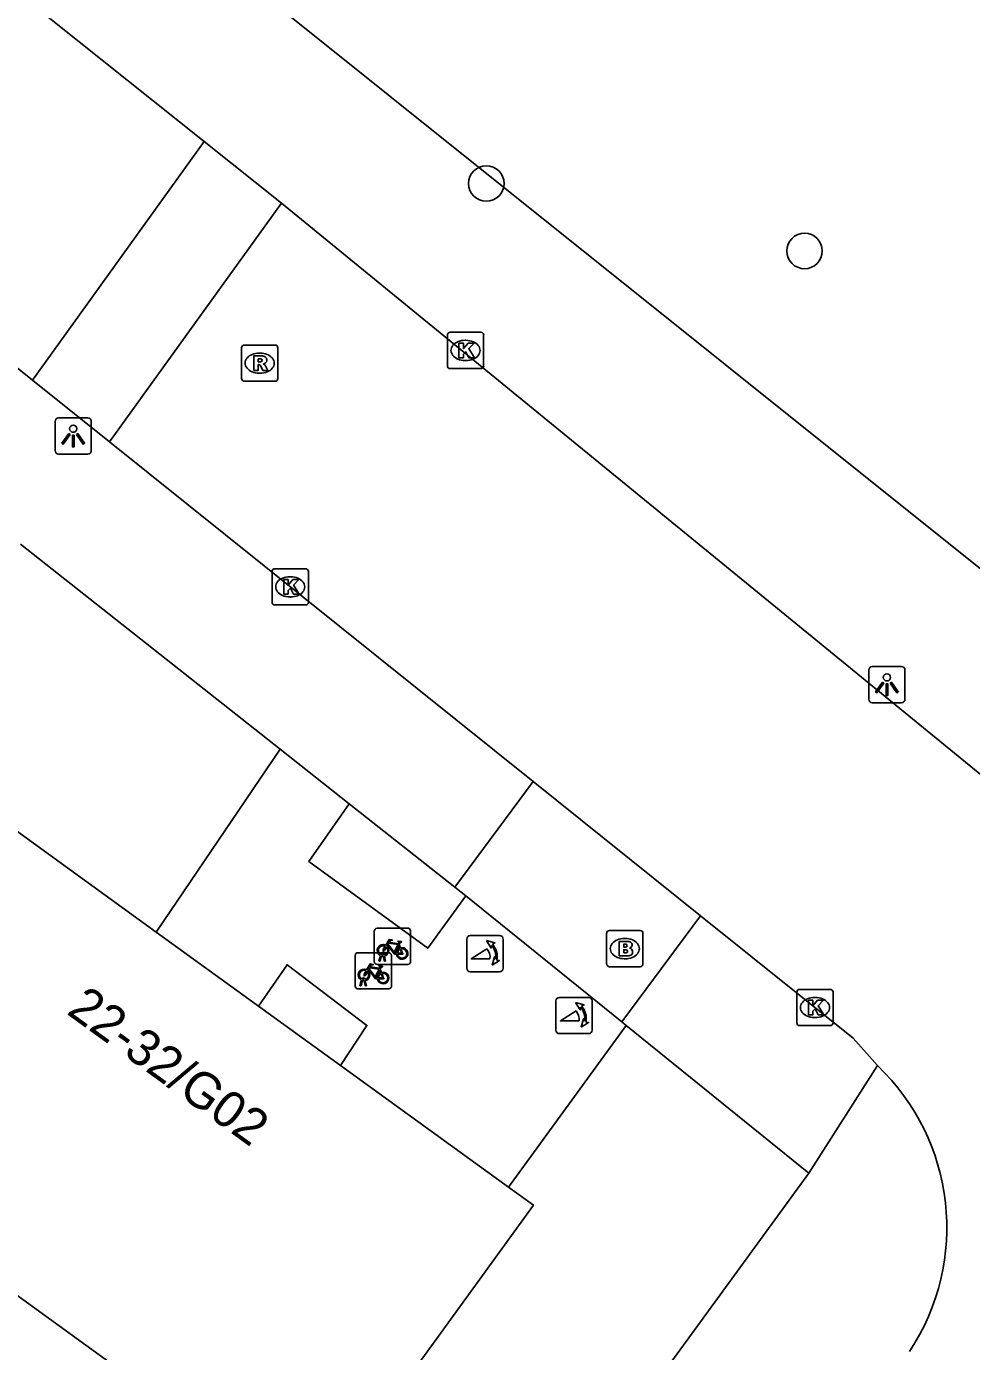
# Model space of a CAD drawing. Extents: x 159675 to 160530, y 382179 to 382901.
# Drawn here: x 160377.56 to 160403.62, y 382615.6 to 382652.14 of the extents above; entities that cross this region are included whole.
import ezdxf

# ---------------------------------------------------------------- set-up
doc = ezdxf.new("R2010")
doc.units = 0
for name, color, linetype in [('IMGEO_Boom', 7, 'Continuous'), ('IMGEO_Brandkraan', 7, 'Continuous'), ('IMGEO_Fietsenrek', 7, 'Continuous'), ('IMGEO_Kolk', 7, 'Continuous'), ('IMGEO_Lichtpunt', 7, 'Continuous'), ('IMGEO_Pand', 7, 'Continuous'), ('IMGEO_Pand_nummerreeks', 7, 'Continuous'), ('IMGEO_Poller', 7, 'Continuous'), ('IMGEO_Rijbaan_lokaal_gesloten', 7, 'Continuous'), ('IMGEO_Rijbaan_lokaal_open', 7, 'Continuous'), ('IMGEO_Rioolput', 7, 'Continuous'), ('IMGEO_Voetpad_open', 7, 'Continuous')]:
    doc.layers.add(name, color=color, linetype=linetype)

msp = doc.modelspace()

# ---------------------------------------------------------------- linework, layer by layer
at = {"layer": 'IMGEO_Boom'}
for centre in [(160390.238, 382647.812), (160399.015, 382645.95)]:
    msp.add_circle(centre, 0.489, dxfattribs=at)
at = {"layer": 'IMGEO_Brandkraan'}
for p, q in [((160393.557, 382626.284), (160393.557, 382627.136)), ((160393.632, 382627.21), (160394.484, 382627.21)), ((160394.045, 382626.99), (160394.07, 382626.99)), ((160394.558, 382627.136), (160394.558, 382626.284)), ((160394.484, 382626.21), (160393.632, 382626.21)), ((160394.068, 382626.43), (160394.043, 382626.43))]:
    msp.add_line(p, q, dxfattribs=at)
for points in [[(160393.557, 382626.284), (160393.557, 382627.136)], [(160393.632, 382627.21), (160394.484, 382627.21)], [(160394.558, 382627.136), (160394.558, 382626.284)], [(160393.905, 382626.91), (160393.905, 382626.51), (160394.118, 382626.51)], [(160394.136, 382626.91), (160393.905, 382626.91)], [(160394.084, 382626.829), (160394.03, 382626.829), (160394.03, 382626.753)], [(160394.03, 382626.753), (160394.083, 382626.753)], [(160394.092, 382626.677), (160394.03, 382626.677), (160394.03, 382626.596)], [(160394.03, 382626.596), (160394.092, 382626.596)], [(160394.484, 382626.21), (160393.632, 382626.21)]]:
    msp.add_lwpolyline(points, dxfattribs=at)
for centre, radius, start, end in [((160393.634, 382627.134), 0.0765, 91.552, 178.448), ((160393.634, 382627.134), 0.0765, 91.552, 178.448), ((160394.482, 382627.134), 0.0765, 1.552, 88.448), ((160394.482, 382627.134), 0.0765, 1.552, 88.448), ((160394.085, 382626.791), 0.0379, 267.8285, 90.9355), ((160394.093, 382626.636), 0.0404, 269.8759, 90.5077), ((160394.14, 382626.765), 0.145, 59.4692, 91.5367), ((160394.165, 382626.812), 0.0922, 285.5137, 58.1501), ((160394.17, 382626.62), 0.105, 301.3115, 78.989), ((160393.634, 382626.286), 0.0765, 181.552, 268.448), ((160393.634, 382626.286), 0.0765, 181.552, 268.448), ((160394.124, 382626.761), 0.251, 268.6676, 293.5347), ((160394.482, 382626.286), 0.0765, 271.552, 358.448), ((160394.482, 382626.286), 0.0765, 271.552, 358.448)]:
    msp.add_arc(centre, radius, start, end, dxfattribs=at)
for centre, major_axis, ratio, start_param, end_param in [((160394.044, 382626.71), (-0.387, 0.002), 0.722429, 4.712389, 7.853982), ((160394.069, 382626.71), (-0.39, 0.002), 0.717154, 1.570796, 4.712389)]:
    msp.add_ellipse(centre, major_axis=major_axis, ratio=ratio, start_param=start_param, end_param=end_param, dxfattribs=at)
at = {"layer": 'IMGEO_Fietsenrek'}
for p, q in [((160387.15, 382626.351), (160387.15, 382627.192)), ((160387.15, 382627.192), (160387.15, 382626.351)), ((160387.225, 382627.276), (160388.066, 382627.276)), ((160388.066, 382627.276), (160387.225, 382627.276)), ((160388.15, 382627.201), (160388.15, 382626.36)), ((160388.15, 382626.36), (160388.15, 382627.201)), ((160386.7, 382626.598), (160387.541, 382626.598)), ((160387.541, 382626.598), (160386.7, 382626.598)), ((160387.837, 382626.825), (160387.873, 382626.73)), ((160386.625, 382625.673), (160386.625, 382626.514)), ((160386.625, 382626.514), (160386.625, 382625.673)), ((160388.075, 382626.276), (160387.234, 382626.276)), ((160387.234, 382626.276), (160388.075, 382626.276)), ((160387.277, 382626.36), (160387.316, 382626.52)), ((160387.311, 382626.36), (160387.277, 382626.36)), ((160387.346, 382626.508), (160387.311, 382626.36)), ((160387.388, 382626.532), (160387.387, 382626.536)), ((160387.429, 382626.36), (160387.395, 382626.502)), ((160387.419, 382626.543), (160387.42, 382626.536)), ((160387.427, 382626.506), (160387.462, 382626.36)), ((160387.462, 382626.36), (160387.429, 382626.36)), ((160387.625, 382626.523), (160387.625, 382625.682)), ((160387.625, 382625.682), (160387.625, 382626.523)), ((160386.752, 382625.682), (160386.791, 382625.842)), ((160386.863, 382625.854), (160386.862, 382625.858)), ((160386.894, 382625.865), (160386.895, 382625.858)), ((160387.312, 382626.147), (160387.348, 382626.052)), ((160387.55, 382625.598), (160386.709, 382625.598)), ((160386.709, 382625.598), (160387.55, 382625.598)), ((160386.786, 382625.682), (160386.752, 382625.682)), ((160386.821, 382625.83), (160386.786, 382625.682)), ((160386.904, 382625.682), (160386.87, 382625.824)), ((160386.902, 382625.828), (160386.937, 382625.682)), ((160386.937, 382625.682), (160386.904, 382625.682))]:
    msp.add_line(p, q, dxfattribs=at)
for points in [[(160387.463, 382626.802), (160387.558, 382626.966), (160387.644, 382626.952), (160387.646, 382626.943), (160387.59, 382626.932), (160387.563, 382626.887), (160387.819, 382626.846)], [(160387.484, 382626.75), (160387.432, 382626.66), (160387.392, 382626.635), (160387.393, 382626.682), (160387.448, 382626.776)], [(160387.759, 382626.558), (160387.709, 382626.558), (160387.518, 382626.809), (160387.499, 382626.777)], [(160387.806, 382626.821), (160387.549, 382626.862), (160387.532, 382626.833), (160387.699, 382626.613), (160387.806, 382626.821)], [(160387.854, 382626.723), (160387.824, 382626.8), (160387.715, 382626.582), (160387.758, 382626.582)], [(160387.788, 382626.582), (160387.908, 382626.581), (160387.864, 382626.695)], [(160387.884, 382626.702), (160387.939, 382626.557), (160387.789, 382626.557)], [(160387.819, 382626.846), (160387.844, 382626.895), (160387.838, 382626.899), (160387.815, 382626.903), (160387.803, 382626.91), (160387.802, 382626.913), (160387.804, 382626.918), (160387.899, 382626.903), (160387.901, 382626.893), (160387.891, 382626.88), (160387.879, 382626.874), (160387.865, 382626.88), (160387.837, 382626.825)], [(160386.938, 382626.124), (160387.033, 382626.288), (160387.119, 382626.274), (160387.121, 382626.265), (160387.065, 382626.254), (160387.038, 382626.209), (160387.294, 382626.168)], [(160387.294, 382626.168), (160387.319, 382626.217), (160387.313, 382626.221), (160387.29, 382626.225), (160387.278, 382626.232), (160387.277, 382626.235), (160387.279, 382626.24), (160387.374, 382626.225), (160387.376, 382626.215), (160387.366, 382626.202), (160387.354, 382626.196), (160387.34, 382626.202), (160387.312, 382626.147)], [(160386.959, 382626.072), (160386.907, 382625.982), (160386.867, 382625.957), (160386.868, 382626.004), (160386.923, 382626.098)], [(160387.234, 382625.88), (160387.184, 382625.88), (160386.993, 382626.131), (160386.974, 382626.099)], [(160387.281, 382626.143), (160387.024, 382626.184), (160387.007, 382626.155), (160387.174, 382625.935), (160387.281, 382626.143)], [(160387.329, 382626.045), (160387.299, 382626.122), (160387.19, 382625.904), (160387.233, 382625.904)], [(160387.263, 382625.904), (160387.383, 382625.903), (160387.339, 382626.017)], [(160387.359, 382626.024), (160387.414, 382625.879), (160387.264, 382625.879)]]:
    msp.add_lwpolyline(points, dxfattribs=at)
for centre, radius, start, end in [((160387.228, 382627.198), 0.0779, 92.4484, 184.2845), ((160387.228, 382627.198), 0.0779, 92.4484, 184.2845), ((160388.072, 382627.198), 0.0779, 2.4484, 94.2845), ((160388.072, 382627.198), 0.0779, 2.4484, 94.2845), ((160386.703, 382626.52), 0.0779, 92.4484, 184.2845), ((160386.703, 382626.52), 0.0779, 92.4484, 184.2845), ((160387.39, 382626.661), 0.159, 62.6766, 242.1369), ((160387.39, 382626.661), 0.129, 63.3192, 238.903), ((160387.37, 382626.532), 0.0499, 12.8025, 158.6934), ((160387.39, 382626.661), 0.129, 283.6043, 43.4302), ((160387.39, 382626.661), 0.159, 283.5766, 46.6042), ((160387.547, 382626.52), 0.0779, 2.4484, 94.2845), ((160387.547, 382626.52), 0.0779, 2.4484, 94.2845), ((160387.917, 382626.577), 0.159, 113.3408, 178.3217), ((160387.917, 382626.577), 0.159, 187.0065, 105.7708), ((160387.917, 382626.577), 0.129, 113.923, 177.9556), ((160387.917, 382626.577), 0.129, 188.6715, 104.5883), ((160387.228, 382626.354), 0.0779, 182.4484, 274.2845), ((160387.228, 382626.354), 0.0779, 182.4484, 274.2845), ((160387.39, 382626.661), 0.159, 253.9967, 271.7867), ((160387.37, 382626.532), 0.0174, 12.8025, 163.4502), ((160387.39, 382626.661), 0.129, 253.415, 269.0204), ((160388.072, 382626.354), 0.0779, 272.4484, 4.2845), ((160388.072, 382626.354), 0.0779, 272.4484, 4.2845), ((160386.865, 382625.983), 0.159, 62.6766, 242.1369), ((160386.865, 382625.983), 0.129, 63.3192, 238.903), ((160386.845, 382625.854), 0.0499, 12.8025, 158.6934), ((160386.845, 382625.854), 0.0174, 12.8025, 163.4502), ((160386.865, 382625.983), 0.129, 253.415, 269.0204), ((160386.865, 382625.983), 0.129, 283.6043, 43.4302), ((160386.865, 382625.983), 0.159, 283.5766, 46.6042), ((160387.392, 382625.899), 0.159, 113.3408, 178.3217), ((160387.392, 382625.899), 0.159, 187.0065, 105.7708), ((160387.392, 382625.899), 0.129, 113.923, 177.9556), ((160387.392, 382625.899), 0.129, 188.6715, 104.5883), ((160386.703, 382625.676), 0.0779, 182.4484, 274.2845), ((160386.703, 382625.676), 0.0779, 182.4484, 274.2845), ((160386.865, 382625.983), 0.159, 253.9967, 271.7867), ((160387.547, 382625.676), 0.0779, 272.4484, 4.2845), ((160387.547, 382625.676), 0.0779, 272.4484, 4.2845)]:
    msp.add_arc(centre, radius, start, end, dxfattribs=at)
at = {"layer": 'IMGEO_Kolk'}
for p, q in [((160389.164, 382642.781), (160389.164, 382643.633)), ((160389.239, 382643.707), (160390.091, 382643.707)), ((160389.652, 382643.487), (160389.677, 382643.487)), ((160390.165, 382643.633), (160390.165, 382642.781)), ((160390.091, 382642.707), (160389.239, 382642.707)), ((160389.675, 382642.927), (160389.65, 382642.927)), ((160384.405, 382637.187), (160385.257, 382637.187)), ((160384.33, 382636.261), (160384.33, 382637.113)), ((160384.818, 382636.967), (160384.843, 382636.967)), ((160385.331, 382637.113), (160385.331, 382636.261)), ((160385.257, 382636.187), (160384.405, 382636.187)), ((160384.841, 382636.407), (160384.816, 382636.407)), ((160398.801, 382624.66), (160398.801, 382625.512)), ((160398.876, 382625.586), (160399.728, 382625.586)), ((160399.802, 382625.512), (160399.802, 382624.66)), ((160399.289, 382625.366), (160399.314, 382625.366)), ((160399.312, 382624.806), (160399.287, 382624.806)), ((160399.728, 382624.586), (160398.876, 382624.586))]:
    msp.add_line(p, q, dxfattribs=at)
for points in [[(160389.164, 382642.781), (160389.164, 382643.633)], [(160389.239, 382643.707), (160390.091, 382643.707)], [(160389.485, 382643.407), (160389.608, 382643.407), (160389.608, 382643.256), (160389.738, 382643.407), (160389.902, 382643.407), (160389.756, 382643.256), (160389.909, 382643.007), (160389.757, 382643.007), (160389.672, 382643.171), (160389.608, 382643.104), (160389.608, 382643.007), (160389.485, 382643.007), (160389.485, 382643.407)], [(160390.165, 382643.633), (160390.165, 382642.781)], [(160390.091, 382642.707), (160389.239, 382642.707)], [(160384.405, 382637.187), (160385.257, 382637.187)], [(160384.33, 382636.261), (160384.33, 382637.113)], [(160384.651, 382636.887), (160384.774, 382636.887), (160384.774, 382636.736), (160384.904, 382636.887), (160385.068, 382636.887), (160384.922, 382636.736), (160385.075, 382636.487), (160384.923, 382636.487), (160384.838, 382636.651), (160384.774, 382636.584), (160384.774, 382636.487), (160384.651, 382636.487), (160384.651, 382636.887)], [(160385.331, 382637.113), (160385.331, 382636.261)], [(160385.257, 382636.187), (160384.405, 382636.187)], [(160398.801, 382624.66), (160398.801, 382625.512)], [(160398.876, 382625.586), (160399.728, 382625.586)], [(160399.802, 382625.512), (160399.802, 382624.66)], [(160399.122, 382625.286), (160399.245, 382625.286), (160399.245, 382625.135), (160399.375, 382625.286), (160399.539, 382625.286), (160399.393, 382625.135), (160399.546, 382624.886), (160399.394, 382624.886), (160399.309, 382625.05), (160399.245, 382624.983), (160399.245, 382624.886), (160399.122, 382624.886), (160399.122, 382625.286)], [(160399.728, 382624.586), (160398.876, 382624.586)]]:
    msp.add_lwpolyline(points, dxfattribs=at)
for centre, start, end in [((160389.241, 382643.631), 91.552, 178.448), ((160389.241, 382643.631), 91.552, 178.448), ((160390.089, 382643.631), 1.552, 88.448), ((160390.089, 382643.631), 1.552, 88.448), ((160389.241, 382642.783), 181.552, 268.448), ((160389.241, 382642.783), 181.552, 268.448), ((160390.089, 382642.783), 271.552, 358.448), ((160390.089, 382642.783), 271.552, 358.448), ((160384.407, 382637.111), 91.552, 178.448), ((160384.407, 382637.111), 91.552, 178.448), ((160385.255, 382637.111), 1.552, 88.448), ((160385.255, 382637.111), 1.552, 88.448), ((160384.407, 382636.263), 181.552, 268.448), ((160384.407, 382636.263), 181.552, 268.448), ((160385.255, 382636.263), 271.552, 358.448), ((160385.255, 382636.263), 271.552, 358.448), ((160398.878, 382625.51), 91.552, 178.448), ((160398.878, 382625.51), 91.552, 178.448), ((160399.726, 382625.51), 1.552, 88.448), ((160399.726, 382625.51), 1.552, 88.448), ((160398.878, 382624.662), 181.552, 268.448), ((160398.878, 382624.662), 181.552, 268.448), ((160399.726, 382624.662), 271.552, 358.448), ((160399.726, 382624.662), 271.552, 358.448)]:
    msp.add_arc(centre, 0.0765, start, end, dxfattribs=at)
for centre, major_axis, ratio, start_param, end_param in [((160389.651, 382643.207), (-0.387, 0.002), 0.722429, 4.712389, 7.853982), ((160389.676, 382643.207), (-0.39, 0.002), 0.717154, 1.570796, 4.712389), ((160384.817, 382636.687), (-0.387, 0.002), 0.722429, 4.712389, 7.853982), ((160384.842, 382636.687), (-0.39, 0.002), 0.717154, 1.570796, 4.712389), ((160399.288, 382625.086), (-0.387, 0.002), 0.722429, 4.712389, 7.853982), ((160399.313, 382625.086), (-0.39, 0.002), 0.717154, 1.570796, 4.712389)]:
    msp.add_ellipse(centre, major_axis=major_axis, ratio=ratio, start_param=start_param, end_param=end_param, dxfattribs=at)
at = {"layer": 'IMGEO_Lichtpunt'}
for p, q in [((160378.349, 382641.251), (160378.349, 382640.444)), ((160378.349, 382641.251), (160378.349, 382640.444)), ((160379.251, 382641.346), (160378.443, 382641.346)), ((160379.251, 382641.346), (160378.443, 382641.346)), ((160379.345, 382640.444), (160379.345, 382641.251)), ((160379.345, 382640.444), (160379.345, 382641.251)), ((160378.443, 382640.35), (160379.251, 382640.35)), ((160378.443, 382640.35), (160379.251, 382640.35)), ((160400.787, 382634.393), (160400.787, 382633.586)), ((160400.787, 382634.393), (160400.787, 382633.586)), ((160401.689, 382634.488), (160400.881, 382634.488)), ((160401.689, 382634.488), (160400.881, 382634.488)), ((160401.783, 382633.586), (160401.783, 382634.393)), ((160401.783, 382633.586), (160401.783, 382634.393)), ((160400.881, 382633.492), (160401.689, 382633.492)), ((160400.881, 382633.492), (160401.689, 382633.492))]:
    msp.add_line(p, q, dxfattribs=at)
for points in [[(160378.723, 382640.915), (160378.762, 382640.887), (160378.574, 382640.625), (160378.536, 382640.652), (160378.723, 382640.915)], [(160378.825, 382640.867), (160378.872, 382640.867), (160378.872, 382640.545), (160378.825, 382640.545), (160378.825, 382640.867)], [(160378.935, 382640.887), (160378.973, 382640.914), (160379.16, 382640.652), (160379.121, 382640.624), (160378.935, 382640.887)], [(160401.161, 382634.057), (160401.2, 382634.029), (160401.012, 382633.767), (160400.974, 382633.794), (160401.161, 382634.057)], [(160401.263, 382634.009), (160401.31, 382634.009), (160401.31, 382633.687), (160401.263, 382633.687), (160401.263, 382634.009)], [(160401.373, 382634.029), (160401.411, 382634.056), (160401.598, 382633.794), (160401.559, 382633.766), (160401.373, 382634.029)]]:
    msp.add_lwpolyline(points, dxfattribs=at)
for centre in [(160378.848, 382641.049), (160401.286, 382634.191)]:
    msp.add_circle(centre, 0.0994, dxfattribs=at)
for centre, start, end in [((160378.443, 382641.251), 90, 180), ((160378.443, 382641.251), 90, 180), ((160379.251, 382641.251), 0, 90), ((160379.251, 382641.251), 0, 90), ((160378.443, 382640.444), 180, 270), ((160378.443, 382640.444), 180, 270), ((160379.251, 382640.444), 270, 0), ((160379.251, 382640.444), 270, 360), ((160400.881, 382634.393), 90, 180), ((160400.881, 382634.393), 90, 180), ((160401.689, 382634.393), 0, 90), ((160401.689, 382634.393), 0, 90), ((160400.881, 382633.586), 180, 270), ((160400.881, 382633.586), 180, 270), ((160401.689, 382633.586), 270, 0), ((160401.689, 382633.586), 270, 360)]:
    msp.add_arc(centre, 0.0946, start, end, dxfattribs=at)
at = {"layer": 'IMGEO_Pand'}
for points in [[(160377.281, 382629.959), (160381.138, 382627.166)], [(160381.138, 382627.166), (160383.956, 382625.125)], [(160386.216, 382623.488), (160383.956, 382625.125)], [(160386.216, 382623.488), (160390.852, 382620.13)], [(160390.852, 382620.13), (160391.536, 382619.635), (160385.454, 382611.238), (160381.405, 382614.171), (160371.199, 382621.562)]]:
    msp.add_lwpolyline(points, dxfattribs=at)
at = {"layer": 'IMGEO_Poller'}
for p, q in [((160389.703, 382626.975), (160389.703, 382626.168)), ((160389.703, 382626.975), (160389.703, 382626.168)), ((160390.605, 382627.07), (160389.797, 382627.07)), ((160390.605, 382627.07), (160389.797, 382627.07)), ((160390.699, 382626.168), (160390.699, 382626.975)), ((160390.699, 382626.168), (160390.699, 382626.975)), ((160389.797, 382626.073), (160390.605, 382626.073)), ((160389.797, 382626.073), (160390.605, 382626.073)), ((160392.16, 382625.267), (160392.16, 382624.46)), ((160392.16, 382625.267), (160392.16, 382624.46)), ((160393.062, 382625.362), (160392.254, 382625.362)), ((160393.062, 382625.362), (160392.254, 382625.362)), ((160393.156, 382624.46), (160393.156, 382625.267)), ((160393.156, 382624.46), (160393.156, 382625.267)), ((160392.254, 382624.365), (160393.062, 382624.365)), ((160392.254, 382624.365), (160393.062, 382624.365))]:
    msp.add_line(p, q, dxfattribs=at)
for points in [[(160390.382, 382626.799), (160390.37, 382626.726), (160390.245, 382626.931)], [(160390.245, 382626.931), (160390.476, 382626.865), (160390.405, 382626.833)], [(160390.338, 382626.426), (160389.825, 382626.426), (160390.255, 382626.701)], [(160390.398, 382626.254), (160390.464, 382626.485), (160390.494, 382626.417)], [(160390.53, 382626.39), (160390.602, 382626.379), (160390.398, 382626.254)], [(160392.839, 382625.091), (160392.827, 382625.018), (160392.702, 382625.223)], [(160392.702, 382625.223), (160392.933, 382625.157), (160392.862, 382625.125)], [(160392.795, 382624.718), (160392.282, 382624.718), (160392.712, 382624.993)], [(160392.855, 382624.546), (160392.921, 382624.777), (160392.951, 382624.709)], [(160392.987, 382624.682), (160393.059, 382624.671), (160392.855, 382624.546)]]:
    msp.add_lwpolyline(points, dxfattribs=at)
for centre, radius, start, end in [((160389.797, 382626.975), 0.0946, 90, 180), ((160389.797, 382626.975), 0.0946, 90, 180), ((160390.605, 382626.975), 0.0946, 0, 90), ((160390.605, 382626.975), 0.0946, 0, 90), ((160390.01, 382626.476), 0.332, 351.3247, 42.4854), ((160390.024, 382626.486), 0.476, 351.7527, 41.1691), ((160390.024, 382626.486), 0.516, 349.3569, 42.2912), ((160389.797, 382626.168), 0.0946, 180, 270), ((160389.797, 382626.168), 0.0946, 180, 270), ((160390.605, 382626.168), 0.0946, 270, 0), ((160390.605, 382626.168), 0.0946, 270, 0), ((160392.254, 382625.267), 0.0946, 90, 180), ((160392.254, 382625.267), 0.0946, 90, 180), ((160392.481, 382624.778), 0.516, 349.3569, 42.2912), ((160393.062, 382625.267), 0.0946, 0, 90), ((160393.062, 382625.267), 0.0946, 0, 90), ((160392.467, 382624.768), 0.332, 351.3247, 42.4854), ((160392.481, 382624.778), 0.476, 351.7527, 41.1691), ((160392.254, 382624.46), 0.0946, 180, 270), ((160392.254, 382624.46), 0.0946, 180, 270), ((160393.062, 382624.46), 0.0946, 270, 0), ((160393.062, 382624.46), 0.0946, 270, 0)]:
    msp.add_arc(centre, radius, start, end, dxfattribs=at)
at = {"layer": 'IMGEO_Rijbaan_lokaal_gesloten'}
for points in [[(160382.462, 382648.966), (160376.836, 382653.466)], [(160406.571, 382629.307), (160384.589, 382647.265)], [(160375.287, 382644.339), (160377.722, 382642.387)], [(160379.847, 382640.684), (160391.528, 382631.318)], [(160391.528, 382631.318), (160396.148, 382627.615)], [(160396.148, 382627.615), (160400.355, 382624.242), (160401.023, 382623.483)]]:
    msp.add_lwpolyline(points, dxfattribs=at)
msp.add_arc((160396.769, 382619.016), 6.169, 326.3585, 46.3936, dxfattribs=at)
at = {"layer": 'IMGEO_Rijbaan_lokaal_open'}
for points in [[(160377.722, 382642.387), (160382.462, 382648.966)], [(160382.462, 382648.966), (160384.589, 382647.265)], [(160384.589, 382647.265), (160379.847, 382640.684)], [(160379.847, 382640.684), (160377.722, 382642.387)]]:
    msp.add_lwpolyline(points, dxfattribs=at)
at = {"layer": 'IMGEO_Rioolput'}
for p, q in [((160383.488, 382642.43), (160383.488, 382643.282)), ((160383.563, 382643.356), (160384.415, 382643.356)), ((160383.976, 382643.136), (160384.001, 382643.136)), ((160384.489, 382643.282), (160384.489, 382642.43)), ((160384.415, 382642.356), (160383.563, 382642.356)), ((160383.999, 382642.576), (160383.974, 382642.576))]:
    msp.add_line(p, q, dxfattribs=at)
for points in [[(160383.488, 382642.43), (160383.488, 382643.282)], [(160383.563, 382643.356), (160384.415, 382643.356)], [(160384.077, 382643.054), (160383.825, 382643.056), (160383.825, 382642.656)], [(160384.489, 382643.282), (160384.489, 382642.43)], [(160383.825, 382642.656), (160383.949, 382642.656), (160383.949, 382642.818), (160383.96, 382642.818)], [(160384.003, 382642.975), (160383.949, 382642.975), (160383.949, 382642.894)], [(160383.949, 382642.894), (160384.001, 382642.894)], [(160384.007, 382642.789), (160384.078, 382642.656), (160384.218, 382642.656), (160384.153, 382642.782)], [(160384.415, 382642.356), (160383.563, 382642.356)]]:
    msp.add_lwpolyline(points, dxfattribs=at)
for centre, radius, start, end in [((160383.565, 382643.28), 0.0765, 91.552, 178.448), ((160383.565, 382643.28), 0.0765, 91.552, 178.448), ((160384.076, 382642.944), 0.109, 350.3612, 89.416), ((160384.413, 382643.28), 0.0765, 1.552, 88.448), ((160384.413, 382643.28), 0.0765, 1.552, 88.448), ((160383.959, 382642.765), 0.0533, 26.0293, 88.6989), ((160383.985, 382643.083), 0.19, 274.7715, 282.9687), ((160384.009, 382642.879), 0.0964, 77.0061, 93.1865), ((160384.023, 382642.936), 0.0378, 276.6634, 79.6772), ((160384.074, 382642.944), 0.112, 277.5842, 350.9817), ((160384.058, 382642.729), 0.108, 29.5134, 73.7905), ((160383.565, 382642.432), 0.0765, 181.552, 268.448), ((160383.565, 382642.432), 0.0765, 181.552, 268.448), ((160384.413, 382642.432), 0.0765, 271.552, 358.448), ((160384.413, 382642.432), 0.0765, 271.552, 358.448)]:
    msp.add_arc(centre, radius, start, end, dxfattribs=at)
for centre, major_axis, ratio, start_param, end_param in [((160383.975, 382642.856), (-0.387, 0.002), 0.722429, 4.712389, 7.853982), ((160384, 382642.856), (-0.39, 0.002), 0.717154, 1.570796, 4.712389)]:
    msp.add_ellipse(centre, major_axis=major_axis, ratio=ratio, start_param=start_param, end_param=end_param, dxfattribs=at)
at = {"layer": 'IMGEO_Voetpad_open'}
for points in [[(160406.072, 382635.422), (160378.286, 382657.664)], [(160377.395, 382637.867), (160384.552, 382632.213)], [(160384.552, 382632.213), (160381.138, 382627.166)], [(160384.552, 382632.213), (160386.458, 382630.707)], [(160389.367, 382628.409), (160391.528, 382631.318)], [(160389.672, 382628.168), (160388.624, 382626.718), (160385.343, 382629.114), (160386.458, 382630.707)], [(160386.458, 382630.707), (160389.367, 382628.409)], [(160389.367, 382628.409), (160389.672, 382628.168)], [(160389.672, 382628.168), (160393.973, 382624.693)], [(160396.148, 382627.615), (160393.973, 382624.693)], [(160383.956, 382625.125), (160384.743, 382626.263), (160386.946, 382624.592), (160386.216, 382623.488)], [(160394.097, 382624.593), (160390.852, 382620.13)], [(160393.973, 382624.693), (160394.097, 382624.593)], [(160399.135, 382620.521), (160394.097, 382624.593)], [(160401.023, 382623.483), (160399.135, 382620.521)], [(160399.135, 382620.521), (160346.474, 382548.259)]]:
    msp.add_lwpolyline(points, dxfattribs=at)

# ---------------------------------------------------------------- texts
at = {"layer": 'IMGEO_Pand_nummerreeks'}
msp.add_text('22-32/G02', height=1, rotation=324.0862, dxfattribs=at).set_placement((160378.636, 382624.928))

doc.saveas('drawing.dxf')
